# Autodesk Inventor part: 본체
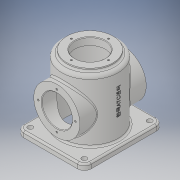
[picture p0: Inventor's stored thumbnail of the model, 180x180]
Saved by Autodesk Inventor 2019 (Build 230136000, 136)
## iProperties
Created: 2020-12
Part Number: 본체
Material: 일반
Document SubType Name: Modeling
Designer: jun-1-11
Density: 1 g/cm^3
Appearance: 기본값
Mass: 457.576 g
Surface Area: 1067.12 cm^2
Volume: 457.576 cm^3
Author: jun-1-11
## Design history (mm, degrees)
sketch "스케치1"
  geometry: L1 (60, 70)-(-60, 70); L2 (-60, 70)-(-60, -70); L3 (-60, -70)-(60, -70); L4 (60, -70)-(60, 70); L5 (60, 70)-(-60, -70); L6 (-60, 70)-(60, -70); 1 further point
  constraints: 12 end point, 2 midpoint, 2 parallel, 1 horizontal, 1 perpendicular
  dimensions: "d0" = 120 distance of L3.end L2.end; "d1" = 140 distance of L2.end L1.end
extrude "돌출1" new body sketch "스케치1" distance "d2" = 10; taper "d3" = 0 deg
fillet "모깎기1" dims "d4" = 12
sketch "스케치2" dims "d19" = 5
  geometry: A1 r 12 centre (-48, 58) between (-48, 70) and (-60, 58) reference; 2 further points
  constraints: 1 coincident
hole "구멍1" sketch "스케치2" at (-48, 58) diameter "d5" = 9; stored, may be unused: countersink angle "d9" = 90 deg, drill point angle "d11" = 0 deg; dims "d6" = 18, "d7" = 4, "d8" = 2, "d10" = 22, "d19" = 5
sketch "스케치3"
  geometry: C1 r 50 at (0, 0); 1 further point
  constraints: 1 centre point, 1 coincident
  dimensions: "d12" = 100 diameter of C1
extrude "돌출2" join sketch "스케치3" distance "d13" = 110; taper "d14" = 0 deg
sketch "스케치5"
  geometry: C1 r 41 at (0, 0); 1 further point
  constraints: 1 centre point, 1 coincident
  dimensions: "d18" = 82 diameter of C1
extrude "돌출4" join sketch "스케치5" distance "d19" = 5; taper "d20" = 0 deg
sketch "스케치6"
  geometry: C1 r 27 at (0, 0); 1 further point
  constraints: 1 centre point, 1 coincident
  dimensions: "d21" = 54 diameter of C1
extrude "돌출5" cut sketch "스케치6" distance "d22" = 13; taper "d23" = 0 deg
sketch "스케치7"
  geometry: L1 (42, 0)-(-42, 0) reference; C1 r 41 at (0, 60); 1 further point
  constraints: 1 centre point, 1 vertical alignment
  dimensions: "d24" = 82 diameter of C1; "d25" = 60 distance from line of L1 C1.centre
extrude "돌출6" join sketch "스케치7" stored distance "d26" = 118; taper "d27" = 0 deg
sketch "스케치8"
  geometry: C1 r 27 at (0, 60); 2 further points
  constraints: 1 centre point, 1 vertical alignment, 1 other
  dimensions: "d28" = 54 diameter of C1; "d29" = 60 distance of point (0, 0) C1.centre
extrude "돌출7" cut sketch "스케치8" stored distance "d30" = 118; taper "d31" = 0 deg
sketch "스케치9"
  geometry: C1 r 42 at (0, 0); 1 further point
  constraints: 1 centre point, 1 coincident
  dimensions: "d32" = 84 diameter of C1
extrude "돌출8" cut sketch "스케치9" distance "d33" = 112; taper "d34" = 0 deg
sketch "스케치10"
  geometry: C1 r 41 at (0, 0) reference; 2 further points
  constraints: 1 vertical alignment
  dimensions: "d35" = 33 distance of C1.centre point (0, 33)
hole "구멍2" sketch "스케치10" at (0, 33) diameter "d36" = 3.242; stored, may be unused: countersink angle "d40" = 90 deg, drill point angle "d42" = 118 deg; dims "d37" = 8, "d38" = 4, "d39" = 2, "d41" = 10
sketch "스케치11"
  geometry: C1 r 41 at (0, 0) reference; 2 further points
  constraints: 1 vertical alignment
  dimensions: "d46" = 33 distance of point (0, 0) point (0, 33)
hole "구멍3" sketch "스케치11" at (0, 33) diameter "d47" = 3.242; stored, may be unused: countersink angle "d51" = 90 deg, drill point angle "d53" = 118 deg; dims "d48" = 8, "d49" = 4, "d50" = 2, "d52" = 10
node "작업 평면1"
sketch "스케치12"
  geometry: L1 (-10, 58)-(-10, -58) reference; 2 further points
  constraints: 1 other
feature "엠보싱1" sketch "스케치12" dims "d0" = 120, "d1" = 140, "d58" = 0.5, "d59" = 0
fillet "모깎기2" dims "d60" = 3
fillet "모깎기3" dims "d61" = 6
chamfer "모따기1" distance "d62" = 1; stored, may be unused: second distance "d63" = 2, angle "d64" = 45 deg
fillet "모깎기4" dims "d65" = 3
node "솔리드1"
mirror "미러1"
mirror "미러2"
pattern_circular "원형 패턴1" dims angle "d44" = 360 deg
mirror "미러3"
pattern_circular "원형 패턴2" dims angle "d55" = 360 deg
